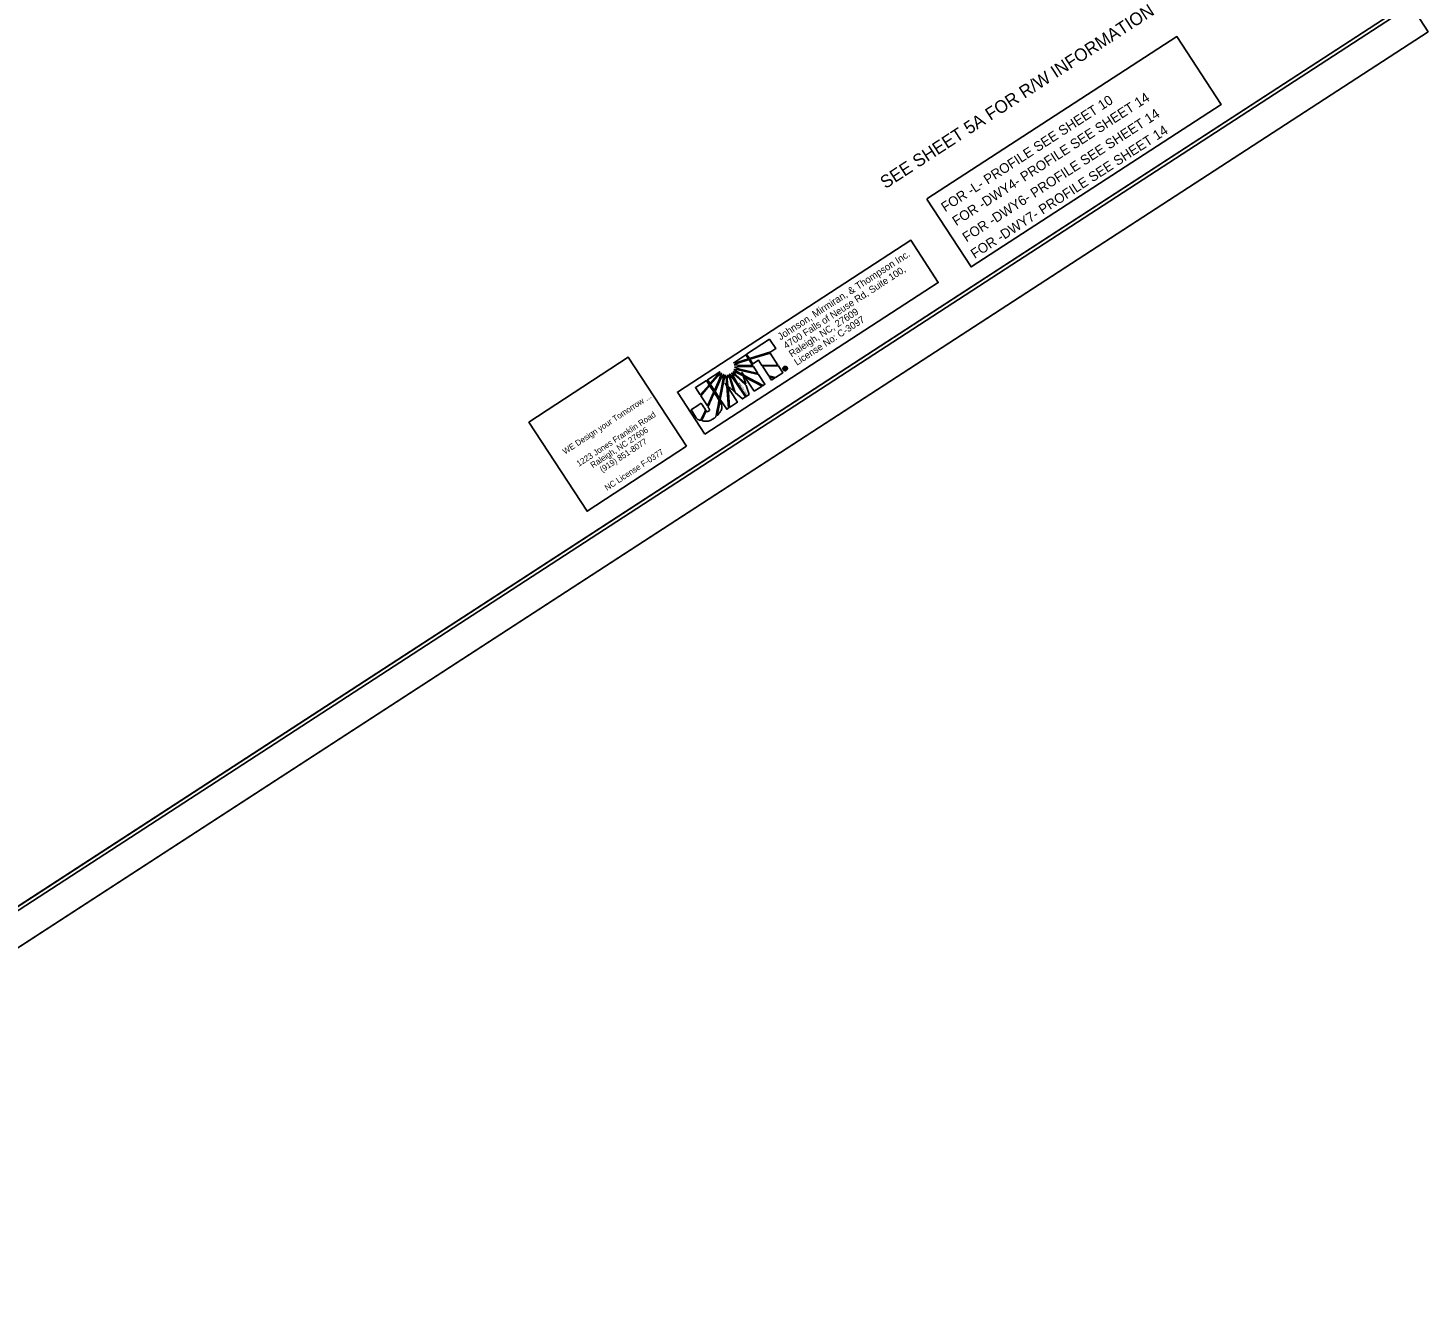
# Model space of a CAD drawing. Extents: x 555170 to 557181, y 503234 to 505074.
# Drawn here: x 556175 to 557181, y 503234 to 504154 of the extents above; entities that cross this region are included whole.
import ezdxf

# ---------------------------------------------------------------- set-up
doc = ezdxf.new("R2010")
doc.units = 0
for name, color, linetype in [('Prop Dimension', 7, 'Continuous'), ('Prop DSN Text', 7, 'Continuous'), ('Prop Horizontal Alignment Curve and Spiral Data', 7, 'Continuous'), ('Sheet Border Standard 30in CELL', 7, 'Continuous'), ('Sheet Clip Boundary CELL', 7, 'Continuous'), ('Sheet Cutting Line CELL', 7, 'Continuous'), ('Sheet Plot Border Inside CELL', 7, 'Continuous'), ('Sheet Plot Border Outside CELL', 7, 'Continuous')]:
    doc.layers.add(name, color=color, linetype=linetype)

msp = doc.modelspace()

# ---------------------------------------------------------------- linework, layer by layer
at = {"layer": 'Prop Dimension'}
for p, q in [((556708.1, 503930.6), (556691.6, 503919.9)), ((556712.5, 503923.9), (556708.1, 503930.6)), ((556709, 503921.6), (556712.5, 503923.9)), ((556691, 503919.5), (556682.3, 503913.8)), ((556682.3, 503913.8), (556685.2, 503914.2)), ((556685.3, 503913.5), (556682.7, 503912.2)), ((556682.7, 503912.2), (556687.7, 503911.7)), ((556685.2, 503914.2), (556692.9, 503916.6)), ((556693.3, 503916), (556685.3, 503913.5)), ((556692.9, 503916.6), (556691, 503919.5)), ((556691.6, 503919.9), (556693.6, 503916.9)), ((556695.9, 503911.8), (556693.3, 503916)), ((556693.6, 503916.8), (556709, 503921.6)), ((556693.6, 503916.9), (556693.6, 503916.8)), ((556708.4, 503920.7), (556693.9, 503916.3)), ((556693.9, 503916.3), (556694, 503916.3)), ((556694, 503916.3), (556696, 503913.1)), ((556696, 503913.1), (556700.1, 503915.7)), ((556700.1, 503915.7), (556702.5, 503911.9)), ((556702.5, 503911.9), (556714, 503912.1)), ((556714, 503912.1), (556708.4, 503920.7)), ((556672.3, 503907.3), (556663.5, 503901.6)), ((556665.3, 503898.8), (556670.7, 503904.9)), ((556671.1, 503904.3), (556665.7, 503898.2)), ((556670.7, 503904.9), (556672.3, 503907.3)), ((556673.5, 503906.2), (556671.1, 503904.3)), ((556671.9, 503901.5), (556673.5, 503906.2)), ((556672.1, 503888.3), (556674.8, 503902.3)), ((556675.4, 503902.1), (556672.6, 503887.5)), ((556674.9, 503905.4), (556672.9, 503902)), ((556674.8, 503902.3), (556674.9, 503905.4)), ((556676.4, 503905.1), (556675.4, 503902.1)), ((556677.1, 503901.9), (556676.4, 503905.1)), ((556678, 503905.1), (556677.7, 503902.1)), ((556677.7, 503902.1), (556678.1, 503897.3)), ((556679.4, 503902.6), (556678, 503905.1)), ((556682.4, 503893.4), (556679.4, 503902.6)), ((556683.9, 503899.6), (556679.5, 503905.6)), ((556679.5, 503905.6), (556680.1, 503902.4)), ((556680.1, 503902.4), (556683.4, 503892.5)), ((556680.8, 503906.5), (556684.4, 503900)), ((556683.5, 503904.6), (556680.8, 503906.5)), ((556681.8, 503907.6), (556683.7, 503905.3)), ((556684.7, 503906.6), (556681.8, 503907.6)), ((556682.5, 503909), (556685.1, 503907.2)), ((556685.6, 503908.8), (556682.5, 503909)), ((556686.8, 503911), (556682.8, 503910.6)), ((556682.8, 503910.6), (556685.7, 503909.4)), ((556691.3, 503897.5), (556683.5, 503904.6)), ((556683.7, 503905.3), (556690.9, 503898.7)), ((556689.1, 503904.3), (556684.7, 503906.6)), ((556685.1, 503907.2), (556688.8, 503905.1)), ((556700.2, 503905.3), (556685.6, 503908.8)), ((556685.7, 503909.4), (556699.6, 503906.1)), ((556696.4, 503911.1), (556686.8, 503911)), ((556687.7, 503911.7), (556695.9, 503911.8)), ((556688.8, 503905.1), (556688.2, 503906.9)), ((556688.2, 503906.9), (556689.7, 503904.7)), ((556690.9, 503898.7), (556689.1, 503904.3)), ((556689.7, 503904.7), (556703.4, 503897.4)), ((556702.7, 503897), (556690.4, 503903.5)), ((556690.4, 503903.5), (556697.1, 503893.3)), ((556699.6, 503906.1), (556696.4, 503911.1)), ((556704.7, 503898.3), (556700.2, 503905.3)), ((556714.4, 503911.5), (556702.9, 503911.3)), ((556702.9, 503911.3), (556707.5, 503904.3)), ((556707.5, 503904.3), (556712.2, 503903.1)), ((556711.5, 503902.6), (556708, 503903.5)), ((556708, 503903.5), (556709.4, 503901.3)), ((556709.4, 503901.3), (556711.5, 503902.6)), ((556712.2, 503903.1), (556717.6, 503906.6)), ((556717.6, 503906.6), (556714.4, 503911.5)), ((556718.4, 503910.9), (556718.6, 503910.7)), ((556718.6, 503910.7), (556718.4, 503910.9)), ((556718.4, 503909.9), (556718.9, 503910.2)), ((556719.1, 503908.7), (556718.4, 503909.9)), ((556719, 503910), (556718.8, 503909.8)), ((556718.8, 503909.8), (556719, 503909.6)), ((556718.9, 503910.2), (556718.9, 503910.3)), ((556718.9, 503910.2), (556719, 503910)), ((556719, 503910), (556718.9, 503910.2)), ((556719, 503910), (556719, 503910)), ((556719, 503909.6), (556719.2, 503909.7)), ((556719.3, 503909.5), (556719.1, 503909.3)), ((556719.1, 503909.3), (556719.4, 503908.9)), ((556719.4, 503908.9), (556719.1, 503908.7)), ((556719.2, 503909.7), (556719.3, 503909.5)), ((556719.3, 503909.5), (556719.2, 503909.7)), ((556719.2, 503909.7), (556719.2, 503909.7)), ((556719.3, 503909.5), (556719.3, 503909.5)), ((556719.9, 503908.5), (556720.1, 503908.3)), ((556720.1, 503908.3), (556719.9, 503908.5)), ((556719.9, 503908.5), (556720, 503908.5)), ((556720.1, 503908.3), (556720.1, 503908.3)), ((556662.7, 503901), (556654.8, 503895.9)), ((556654.8, 503895.9), (556658.2, 503890.7)), ((556658.2, 503890.7), (556664.7, 503898)), ((556665, 503897.4), (556658.6, 503890.1)), ((556664.7, 503898), (556662.7, 503901)), ((556663.4, 503882.8), (556668, 503892.9)), ((556663.5, 503901.6), (556665.3, 503898.8)), ((556668, 503892.9), (556665, 503897.4)), ((556665.7, 503898.2), (556668.5, 503893.9)), ((556668.5, 503893.9), (556671.9, 503901.5)), ((556672.9, 503902), (556668.9, 503893.2)), ((556668.9, 503893.2), (556672.1, 503888.3)), ((556677.4, 503897), (556676.1, 503899.1)), ((556676.1, 503899.1), (556677.4, 503897.9)), ((556677.4, 503897.9), (556677.1, 503901.9)), ((556678.6, 503881.2), (556677.4, 503897)), ((556678.1, 503897.3), (556682.4, 503893.4)), ((556685, 503885.4), (556678.2, 503895.9)), ((556678.2, 503895.9), (556679.2, 503881.6)), ((556683.4, 503892.5), (556688.5, 503887.8)), ((556690.7, 503889.2), (556683.9, 503899.6)), ((556684.4, 503900), (556691.3, 503889.5)), ((556693.4, 503891), (556691.3, 503897.5)), ((556697.1, 503893.3), (556702.7, 503897)), ((556703.4, 503897.4), (556704.7, 503898.3)), ((556658.6, 503890.1), (556663.4, 503882.8)), ((556672.6, 503887.5), (556677.3, 503880.4)), ((556679.2, 503881.6), (556685, 503885.4)), ((556688.5, 503887.8), (556690.7, 503889.2)), ((556691.3, 503889.5), (556693.4, 503891)), ((556677.3, 503880.4), (556678.6, 503881.2))]:
    msp.add_line(p, q, dxfattribs=at)
msp.add_lwpolyline([(556661.5, 503862.4), (556829.2, 503971.4), (556809.6, 504001.7), (556641.8, 503892.7)], close=True, dxfattribs=at)
for points in [[(556708.1, 503930.6), (556691.6, 503919.9), (556693.6, 503916.9), (556693.6, 503916.8), (556709, 503921.6), (556712.5, 503923.9), (556708.1, 503930.6)], [(556685.2, 503914.2), (556692.9, 503916.6), (556691, 503919.5), (556682.3, 503913.8), (556685.2, 503914.2)], [(556682.7, 503912.2), (556687.7, 503911.7), (556695.9, 503911.8), (556693.3, 503916), (556685.3, 503913.5), (556682.7, 503912.2)], [(556693.9, 503916.3), (556694, 503916.3), (556696, 503913.1), (556700.1, 503915.7), (556702.5, 503911.9), (556714, 503912.1), (556708.4, 503920.7), (556693.9, 503916.3)], [(556670.7, 503904.9), (556672.3, 503907.3), (556663.5, 503901.6), (556665.3, 503898.8), (556670.7, 503904.9)], [(556665.7, 503898.2), (556668.5, 503893.9), (556671.9, 503901.5), (556673.5, 503906.2), (556671.1, 503904.3), (556665.7, 503898.2)], [(556668.9, 503893.2), (556672.1, 503888.3), (556674.8, 503902.3), (556674.9, 503905.4), (556672.9, 503902), (556668.9, 503893.2)], [(556676.4, 503905.1), (556675.4, 503902.1), (556672.6, 503887.5), (556677.3, 503880.4), (556678.6, 503881.2), (556677.4, 503897), (556676.1, 503899.1), (556677.4, 503897.9), (556677.1, 503901.9), (556676.4, 503905.1)], [(556678, 503905.1), (556677.7, 503902.1), (556678.1, 503897.3), (556682.4, 503893.4), (556679.4, 503902.6), (556678, 503905.1)], [(556680.1, 503902.4), (556683.4, 503892.5), (556688.5, 503887.8), (556690.7, 503889.2), (556683.9, 503899.6), (556679.5, 503905.6), (556680.1, 503902.4)], [(556680.8, 503906.5), (556684.4, 503900), (556691.3, 503889.5), (556693.4, 503891), (556691.3, 503897.5), (556683.5, 503904.6), (556680.8, 503906.5)], [(556681.8, 503907.6), (556683.7, 503905.3), (556690.9, 503898.7), (556689.1, 503904.3), (556684.7, 503906.6), (556681.8, 503907.6)], [(556682.5, 503909), (556685.1, 503907.2), (556688.8, 503905.1), (556688.2, 503906.9), (556689.7, 503904.7), (556703.4, 503897.4), (556704.7, 503898.3), (556700.2, 503905.3), (556685.6, 503908.8), (556682.5, 503909)], [(556682.8, 503910.6), (556685.7, 503909.4), (556699.6, 503906.1), (556696.4, 503911.1), (556686.8, 503911), (556682.8, 503910.6)], [(556697.1, 503893.3), (556702.7, 503897), (556690.4, 503903.5), (556697.1, 503893.3)], [(556702.9, 503911.3), (556707.5, 503904.3), (556712.2, 503903.1), (556717.6, 503906.6), (556714.4, 503911.5), (556702.9, 503911.3), (556702.9, 503911.3)], [(556709.4, 503901.3), (556709.4, 503901.3), (556711.5, 503902.6), (556708, 503903.5), (556709.4, 503901.3)], [(556720, 503909.6), (556720, 503909.6), (556720.1, 503909.5), (556720.1, 503909.5), (556720.2, 503909.4), (556720, 503909.2)], [(556658.2, 503890.7), (556664.7, 503898), (556662.7, 503901), (556654.8, 503895.9), (556658.2, 503890.7)], [(556663.4, 503882.8), (556668, 503892.9), (556665, 503897.4), (556658.6, 503890.1), (556663.4, 503882.8)], [(556679.2, 503881.6), (556685, 503885.4), (556678.2, 503895.9), (556679.2, 503881.6)]]:
    msp.add_lwpolyline(points, dxfattribs=at)
for points, degree in [([(556720.1, 503908.3), (556719.8, 503908), (556719.4, 503908), (556718.9, 503908.1), (556718.5, 503908.1), (556718.2, 503908.4), (556717.9, 503908.7), (556717.7, 503909.1), (556717.6, 503909.5), (556717.7, 503909.9), (556717.8, 503910.3), (556718, 503910.7), (556718.4, 503910.9)], 3), ([(556718.6, 503910.7), (556718.3, 503910.5), (556718.1, 503910.2), (556718, 503909.9), (556717.9, 503909.5), (556718, 503909.2), (556718.2, 503908.9), (556718.4, 503908.6), (556718.7, 503908.4), (556719, 503908.4), (556719.3, 503908.3), (556719.6, 503908.4), (556719.9, 503908.5)], 3), ([(556718.4, 503910.9), (556718.8, 503911.2), (556719.2, 503911.2), (556719.6, 503911.2), (556720, 503911.1), (556720.3, 503910.9), (556720.6, 503910.5)], 3), ([(556720, 503908.5), (556720.2, 503908.7), (556720.4, 503909), (556720.5, 503909.3), (556720.6, 503909.7), (556720.5, 503910), (556720.3, 503910.3), (556720.1, 503910.6), (556719.9, 503910.8), (556719.5, 503910.9), (556719.2, 503910.9), (556718.9, 503910.9), (556718.6, 503910.7)], 3), ([(556718.9, 503910.3), (556719.2, 503910.5), (556719.5, 503910.4), (556719.6, 503910.2), (556719.7, 503910.1), (556719.7, 503910), (556719.7, 503909.8)], 3), ([(556719.2, 503909.7), (556719.4, 503909.8), (556719.4, 503909.9), (556719.4, 503910), (556719.3, 503910.1), (556719.2, 503910.1), (556719, 503910)], 3), ([(556719.6, 503909.6), (556719.5, 503909.6), (556719.5, 503909.6), (556719.3, 503909.5)], 2), ([(556720, 503909.2), (556719.9, 503909.3), (556719.8, 503909.3), (556719.8, 503909.4), (556719.7, 503909.5), (556719.6, 503909.6), (556719.6, 503909.6)], 3), ([(556719.7, 503909.8), (556719.8, 503909.9), (556719.9, 503909.8), (556720, 503909.6)], 2), ([(556720.6, 503910.5), (556720.8, 503910.1), (556720.9, 503909.7), (556720.8, 503909.3), (556720.7, 503908.9), (556720.5, 503908.5), (556720.1, 503908.3)], 3), ([(556664.3, 503878.9), (556663.8, 503878.6), (556663.3, 503878.6), (556662.5, 503879.3), (556662.5, 503879.3), (556659.2, 503872.2), (556659.2, 503872.2), (556662.1, 503871.5), (556665.6, 503872.2), (556667.9, 503873.7), (556668.5, 503874.1), (556669, 503874.5), (556669.5, 503875), (556669.5, 503875), (556671.8, 503886.9), (556671.8, 503886.9), (556671.8, 503886.9), (556668.4, 503892.2), (556668.4, 503892.2), (556668.4, 503892.2), (556663.8, 503882.1), (556663.8, 503882.1), (556665.1, 503880.1), (556665, 503879.3), (556664.3, 503878.9)], 3), ([(556664.3, 503878.9), (556663.8, 503878.6), (556663.3, 503878.6), (556662.5, 503879.3), (556662.5, 503879.3), (556659.2, 503872.2), (556659.2, 503872.2), (556662.1, 503871.5), (556665.6, 503872.2), (556667.9, 503873.7), (556668.5, 503874.1), (556669, 503874.5), (556669.5, 503875), (556669.5, 503875), (556671.8, 503886.9), (556671.8, 503886.9), (556671.8, 503886.9), (556668.4, 503892.2), (556668.4, 503892.2), (556668.4, 503892.2), (556663.8, 503882.1), (556663.8, 503882.1), (556665.1, 503880.1), (556665, 503879.3), (556664.3, 503878.9)], 3), ([(556658.9, 503884.7), (556658.9, 503884.7), (556651.7, 503880), (556651.7, 503880), (556651.7, 503880), (556654.6, 503875.4), (556654.6, 503875.4), (556654.6, 503875.4), (556654.9, 503874.9), (556654.9, 503874.9), (556655.9, 503873.5), (556657.1, 503872.7), (556658.5, 503872.3), (556658.5, 503872.3), (556662.1, 503879.8), (556662.1, 503879.9), (556662.1, 503879.9), (556658.9, 503884.7), (556658.9, 503884.7)], 3), ([(556672.4, 503886.1), (556672.4, 503886.1), (556670.4, 503875.8), (556670.4, 503875.8), (556672.9, 503878.5), (556674.6, 503882.4), (556672.4, 503886.1)], 3)]:
    msp.add_open_spline(points, degree=degree, dxfattribs=at)
at = {"layer": 'Prop DSN Text'}
msp.add_lwpolyline([(556648.4, 503853.8), (556577, 503807.1), (556535.2, 503871), (556606.5, 503917.7)], close=True, dxfattribs=at)
at = {"layer": 'Prop Horizontal Alignment Curve and Spiral Data'}
msp.add_lwpolyline([(556821.1, 504031.3), (556852.8, 503982.6), (557032.4, 504099.2), (557000.7, 504148), (556821.1, 504031.4)], dxfattribs=at)
at = {"layer": 'Sheet Border Standard 30in CELL'}
msp.add_lwpolyline([(556581.3, 505043.8), (555323.3, 504226.8), (555895.2, 503346.2), (557153.2, 504163.2)], close=True, dxfattribs=at)
at = {"layer": 'Sheet Clip Boundary CELL'}
msp.add_lwpolyline([(555838.5, 503433.5), (555757.6, 503602.9), (555641.4, 503854.9), (555665.1, 503867.4), (555636.4, 503915.7), (555617.1, 503909), (555456.4, 504257.6), (555437.1, 504299.2), (556413.5, 504934.8), (556427.1, 504820.4), (556498.5, 504667.6), (556631.8, 504743), (556936.9, 504379.3), (557153.2, 504163.2), (555896, 503346.8)], close=True, dxfattribs=at)
at = {"layer": 'Sheet Cutting Line CELL'}
msp.add_line((555768.7, 503234.3), (557181.1, 504151.5), dxfattribs=at)
at = {"layer": 'Sheet Plot Border Inside CELL'}
msp.add_lwpolyline([(556590.4, 505052.7), (555192.8, 504145.1), (555767.4, 503260.2), (557165.1, 504167.9)], close=True, dxfattribs=at)
at = {"layer": 'Sheet Plot Border Outside CELL'}
msp.add_lwpolyline([(556581.9, 505074), (555169.6, 504156.8), (555768.7, 503234.3), (557181.1, 504151.5)], close=True, dxfattribs=at)

# ---------------------------------------------------------------- texts
at = {"layer": 'Prop Dimension'}
for s, height, rotation, p in [('Johnson, Mirmiran, & Thompson Inc.', 5.111, 33.0007, (556715.9, 503929.8)), ('4700 Falls of Neuse Rd, Suite 100, ', 4.965, 33.0007, (556720, 503923.5)), ('Raleigh, NC, 27609', 4.965, 33.0007, (556723.9, 503917.6)), ('License No: C-3097', 4.965, 33.0007, (556727.7, 503911.6)), ('www.jmt.com', 1.241, 303.0007, (556685.7, 503899.3))]:
    msp.add_text(s, height=height, rotation=rotation, dxfattribs=at).set_placement(p)
at = {"layer": 'Prop DSN Text'}
for s, p in [('WE Design your Tomorrow ...', (556561.1, 503847.8)), ('1223 Jones Franklin Road', (556571.1, 503839)), ('Raleigh, NC 27606', (556581.1, 503838)), ('(919) 851-8077', (556587.9, 503834.8)), ('NC License F-0377', (556591.3, 503821.7))]:
    msp.add_text(s, height=4.267, rotation=33.231, dxfattribs=at).set_placement(p)
at = {"layer": 'Prop Horizontal Alignment Curve and Spiral Data'}
for s, height, p in [('SEE SHEET 5A FOR R/W INFORMATION', 9.1, (556791.3, 504038.4)), ('FOR -L- PROFILE SEE SHEET 10', 7, (556834.2, 504021.8)), ('FOR -DWY4- PROFILE SEE SHEET 14', 7, (556842.2, 504011.8)), ('FOR -DWY6- PROFILE SEE SHEET 14', 7, (556849.5, 504000.2)), ('FOR -DWY7- PROFILE SEE SHEET 14', 7, (556855.4, 503988.3))]:
    msp.add_text(s, height=height, rotation=33.0007, dxfattribs=at).set_placement(p)

doc.saveas('drawing.dxf')
